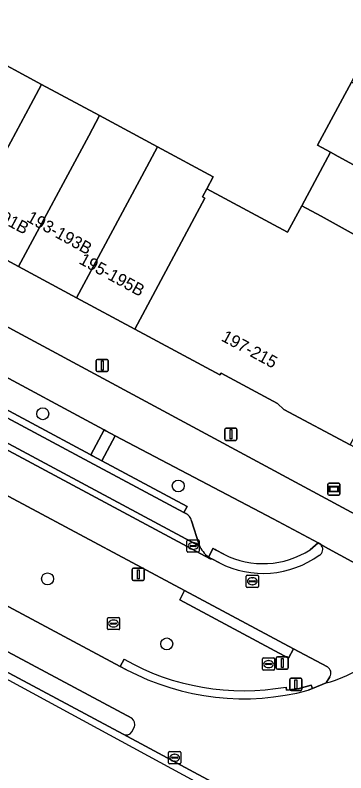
# Model space of a CAD drawing. Extents: x 159489 to 160304, y 383825 to 384531.
# Drawn here: x 159768.9 to 159796, y 383997.9 to 384059.9 of the extents above; entities that cross this region are included whole.
import ezdxf

# ---------------------------------------------------------------- set-up
doc = ezdxf.new("R2010")
doc.units = 0
for name, color, linetype in [('IMGEO_Berm_groen', 7, 'Continuous'), ('IMGEO_Berm_open', 7, 'Continuous'), ('IMGEO_Boom', 7, 'Continuous'), ('IMGEO_Erf', 7, 'Continuous'), ('IMGEO_Fietspad_gesloten', 7, 'Continuous'), ('IMGEO_Groenvoorziening', 7, 'Continuous'), ('IMGEO_Haag', 7, 'Continuous'), ('IMGEO_Informatiebord', 7, 'Continuous'), ('IMGEO_Kolk', 7, 'Continuous'), ('IMGEO_Lichtmast', 7, 'Continuous'), ('IMGEO_OVBaan_gesloten', 7, 'Continuous'), ('IMGEO_Pand', 7, 'Continuous'), ('IMGEO_Pand_nummerreeks', 7, 'Continuous'), ('IMGEO_Parkeervlak_open', 7, 'Continuous'), ('IMGEO_Rijbaan_lokaal_gesloten', 7, 'Continuous'), ('IMGEO_Rijbaan_lokaal_open', 7, 'Continuous'), ('IMGEO_Rioolput', 7, 'Continuous'), ('IMGEO_Verkeersbordpaal', 7, 'Continuous'), ('IMGEO_Voetpad_open', 7, 'Continuous')]:
    doc.layers.add(name, color=color, linetype=linetype)

msp = doc.modelspace()

# ---------------------------------------------------------------- linework, layer by layer
at = {"layer": 'IMGEO_Berm_groen'}
for points in [[(159694.802, 384052.841), (159693.976, 384051.25), (159777.482, 384006.579), (159777.79, 384007.155)], [(159794.454, 384006.529), (159791.668, 384008.018), (159791.261, 384007.258), (159782.348, 384012.022), (159782.754, 384012.782), (159722.71, 384044.871)], [(159777.06, 384025.441), (159775.963, 384023.407), (159782.969, 384019.664), (159782.699, 384019.159), (159782.841, 384019.083)], [(159793.026, 384016.123), (159793.68, 384016.677), (159789.993, 384018.658), (159777.06, 384025.441)], [(159783.314, 384018.492), (159783.95, 384016.527)], [(159784.719, 384015.525), (159785.101, 384016.235), (159785.176, 384016.179), (159785.254, 384016.128), (159785.335, 384016.083), (159785.966, 384015.746)], [(159791.06, 384004.885), (159791.106, 384004.627), (159792.127, 384004.778), (159793.112, 384005.034), (159793.224, 384004.76), (159794.349, 384005.218), (159794.65, 384005.731)]]:
    msp.add_lwpolyline(points, dxfattribs=at)
msp.add_lwpolyline([(159766.543, 384031.098), (159765.444, 384029.028), (159775.012, 384023.915), (159775.067, 384023.886), (159776.158, 384025.928), (159776.103, 384025.957)], close=True, dxfattribs=at)
for centre, radius, start, end in [((159782.548, 384018.364), 0.777, 9.50484, 67.83841), ((159785.919, 384017.242), 2.095, 199.95624, 235.05372), ((159789.168, 384022.07), 7.089, 243.14438, 302.96893), ((159787.583, 384024.482), 19.903, 240.52457, 280.06102), ((159794.145, 384006.03), 0.587, 329.35936, 58.23961), ((159791.413, 384010.841), 16.842, 277.89643, 321.28629)]:
    msp.add_arc(centre, radius, start, end, dxfattribs=at)
at = {"layer": 'IMGEO_Berm_open'}
for points in [[(159785.966, 384015.746), (159785.335, 384016.083), (159785.254, 384016.128), (159785.176, 384016.179), (159785.101, 384016.235), (159784.719, 384015.525)], [(159793.974, 384016.452), (159793.901, 384016.538), (159793.788, 384016.619), (159793.765, 384016.631), (159793.68, 384016.677), (159793.026, 384016.123)], [(159784.967, 384015.376), (159785.598, 384015.039)], [(159777.79, 384007.155), (159777.482, 384006.579), (159777.995, 384006.304)], [(159792.881, 384004.62), (159793.224, 384004.76), (159793.112, 384005.034), (159792.127, 384004.778), (159791.106, 384004.627), (159791.06, 384004.885)]]:
    msp.add_lwpolyline(points, dxfattribs=at)
msp.add_lwpolyline([(159782.754, 384012.782), (159782.348, 384012.022), (159791.261, 384007.258), (159791.668, 384008.018)], close=True, dxfattribs=at)
for centre, radius, start, end in [((159793.533, 384016.149), 0.535, 298.21231, 34.51677), ((159789.169, 384022.064), 7.881, 243.05287, 305.85797), ((159789.168, 384022.07), 7.089, 243.14438, 302.96893), ((159785.839, 384017.108), 1.939, 234.72478, 243.27978), ((159787.583, 384024.482), 19.903, 240.52457, 280.06102), ((159787.586, 384024.445), 20.52, 242.13668, 284.95487)]:
    msp.add_arc(centre, radius, start, end, dxfattribs=at)
at = {"layer": 'IMGEO_Boom'}
for centre in [(159771.136, 384027.249), (159782.231, 384021.336), (159771.522, 384013.734), (159781.289, 384008.412)]:
    msp.add_circle(centre, 0.489, dxfattribs=at)
at = {"layer": 'IMGEO_Erf'}
msp.add_lwpolyline([(159766.267, 384056.759), (159771.029, 384054.198), (159775.785, 384051.64), (159780.536, 384049.085), (159785.098, 384046.631), (159784.572, 384045.652), (159791.189, 384042.093), (159792.356, 384044.263), (159794.711, 384048.642), (159793.646, 384049.235), (159796.419, 384054.39), (159798.849, 384058.909), (159801.215, 384063.308)], dxfattribs=at)
at = {"layer": 'IMGEO_Fietspad_gesloten'}
for points in [[(159731.166, 384054.292), (159729.77, 384050.977), (159731.079, 384050.354), (159731.013, 384050.208), (159744.588, 384042.906), (159745.526, 384042.402), (159755.319, 384037.135), (159756.08, 384036.725), (159765.597, 384031.607), (159765.779, 384031.509), (159766.543, 384031.098), (159776.103, 384025.957), (159776.158, 384025.928), (159776.288, 384025.857), (159777.06, 384025.441), (159789.993, 384018.658), (159793.68, 384016.677), (159793.765, 384016.631), (159793.788, 384016.619), (159793.901, 384016.538), (159794.526, 384016.198), (159800.871, 384012.75), (159801.63, 384012.412), (159802.497, 384011.87)], [(159802.594, 384011.19), (159802.971, 384011.597), (159804.049, 384012.761), (159805.225, 384014.454), (159801.988, 384016.22), (159797.098, 384018.803), (159731.166, 384054.292)]]:
    msp.add_lwpolyline(points, dxfattribs=at)
at = {"layer": 'IMGEO_Groenvoorziening'}
for points in [[(159778.419, 384002.326), (159655.116, 384068.233), (159654.047, 384068.903), (159653.178, 384069.297)], [(159695.057, 384045.182), (159777.713, 384001.02)], [(159778.427, 384001.208), (159778.632, 384001.6)]]:
    msp.add_lwpolyline(points, dxfattribs=at)
for centre, radius, start, end in [((159778.095, 384001.837), 0.587, 336.23603, 56.46612), ((159777.966, 384001.507), 0.549, 242.50607, 326.99685)]:
    msp.add_arc(centre, radius, start, end, dxfattribs=at)
at = {"layer": 'IMGEO_Haag'}
for points in [[(159778.419, 384002.326), (159655.116, 384068.233), (159654.047, 384068.903), (159653.178, 384069.297)], [(159695.057, 384045.182), (159777.713, 384001.02)], [(159778.427, 384001.208), (159778.632, 384001.6)]]:
    msp.add_lwpolyline(points, dxfattribs=at)
for centre, radius, start, end in [((159778.095, 384001.837), 0.587, 336.23603, 56.46612), ((159777.966, 384001.507), 0.549, 242.50607, 326.99685)]:
    msp.add_arc(centre, radius, start, end, dxfattribs=at)
at = {"layer": 'IMGEO_Informatiebord'}
for p, q in [((159794.485, 384020.677), (159794.485, 384021.477)), ((159794.485, 384021.477), (159794.485, 384020.677)), ((159794.585, 384021.577), (159795.375, 384021.577)), ((159795.375, 384021.577), (159794.585, 384021.577)), ((159795.475, 384021.477), (159795.475, 384020.677)), ((159795.475, 384020.677), (159795.475, 384021.477)), ((159795.375, 384020.577), (159794.585, 384020.577)), ((159794.585, 384020.577), (159795.375, 384020.577))]:
    msp.add_line(p, q, dxfattribs=at)
for points in [[(159794.586, 384021.309), (159795.374, 384021.309), (159795.374, 384020.845), (159794.586, 384020.845), (159794.586, 384021.309)], [(159794.651, 384021.244), (159794.651, 384020.91), (159795.309, 384020.91), (159795.309, 384021.244), (159794.651, 384021.244)]]:
    msp.add_lwpolyline(points, dxfattribs=at)
for centre, start, end in [((159794.585, 384021.477), 90, 180), ((159794.585, 384021.477), 90, 180), ((159795.375, 384021.477), 0, 90), ((159795.375, 384021.477), 360, 90), ((159794.585, 384020.677), 180, 270), ((159794.585, 384020.677), 180, 270), ((159795.375, 384020.677), 270, 0), ((159795.375, 384020.677), 270, 0)]:
    msp.add_arc(centre, 0.1, start, end, dxfattribs=at)
at = {"layer": 'IMGEO_Kolk'}
for p, q in [((159782.946, 384015.998), (159782.946, 384016.85)), ((159783.021, 384016.924), (159783.873, 384016.924)), ((159783.947, 384016.85), (159783.947, 384015.998)), ((159783.205, 384016.418), (159783.205, 384016.43)), ((159783.643, 384016.381), (159783.245, 384016.381)), ((159783.248, 384016.467), (159783.646, 384016.467)), ((159783.434, 384016.704), (159783.459, 384016.704)), ((159783.689, 384016.43), (159783.689, 384016.418)), ((159783.873, 384015.924), (159783.021, 384015.924)), ((159783.457, 384016.144), (159783.432, 384016.144)), ((159787.801, 384013.114), (159787.801, 384013.966)), ((159787.876, 384014.04), (159788.728, 384014.04)), ((159788.289, 384013.82), (159788.314, 384013.82)), ((159788.802, 384013.966), (159788.802, 384013.114)), ((159788.06, 384013.534), (159788.06, 384013.546)), ((159788.498, 384013.497), (159788.1, 384013.497)), ((159788.103, 384013.583), (159788.501, 384013.583)), ((159788.312, 384013.26), (159788.287, 384013.26)), ((159788.544, 384013.546), (159788.544, 384013.534)), ((159788.728, 384013.04), (159787.876, 384013.04)), ((159776.426, 384009.654), (159776.426, 384010.506)), ((159776.501, 384010.58), (159777.353, 384010.58)), ((159776.685, 384010.074), (159776.685, 384010.086)), ((159777.123, 384010.037), (159776.725, 384010.037)), ((159776.728, 384010.123), (159777.126, 384010.123)), ((159776.914, 384010.36), (159776.939, 384010.36)), ((159777.169, 384010.086), (159777.169, 384010.074)), ((159777.427, 384010.506), (159777.427, 384009.654)), ((159777.353, 384009.58), (159776.501, 384009.58)), ((159776.937, 384009.8), (159776.912, 384009.8)), ((159789.124, 384006.338), (159789.124, 384007.19)), ((159789.199, 384007.264), (159790.051, 384007.264)), ((159789.612, 384007.044), (159789.637, 384007.044)), ((159790.125, 384007.19), (159790.125, 384006.338)), ((159789.383, 384006.758), (159789.383, 384006.77)), ((159789.821, 384006.721), (159789.423, 384006.721)), ((159789.426, 384006.807), (159789.824, 384006.807)), ((159789.635, 384006.484), (159789.61, 384006.484)), ((159789.867, 384006.77), (159789.867, 384006.758)), ((159790.051, 384006.264), (159789.199, 384006.264))]:
    msp.add_line(p, q, dxfattribs=at)
for points in [[(159782.946, 384015.998), (159782.946, 384016.85)], [(159783.021, 384016.924), (159783.873, 384016.924)], [(159783.947, 384016.85), (159783.947, 384015.998)], [(159783.873, 384015.924), (159783.021, 384015.924)], [(159787.801, 384013.114), (159787.801, 384013.966)], [(159787.876, 384014.04), (159788.728, 384014.04)], [(159788.802, 384013.966), (159788.802, 384013.114)], [(159788.728, 384013.04), (159787.876, 384013.04)], [(159776.426, 384009.654), (159776.426, 384010.506)], [(159776.501, 384010.58), (159777.353, 384010.58)], [(159777.427, 384010.506), (159777.427, 384009.654)], [(159777.353, 384009.58), (159776.501, 384009.58)], [(159789.124, 384006.338), (159789.124, 384007.19)], [(159789.199, 384007.264), (159790.051, 384007.264)], [(159790.125, 384007.19), (159790.125, 384006.338)], [(159790.051, 384006.264), (159789.199, 384006.264)]]:
    msp.add_lwpolyline(points, dxfattribs=at)
for centre, radius, start, end in [((159783.023, 384016.848), 0.0765, 91.55205, 178.44795), ((159783.023, 384016.848), 0.0765, 91.55205, 178.44795), ((159783.871, 384016.848), 0.0765, 1.55205, 88.44795), ((159783.871, 384016.848), 0.0765, 1.55205, 88.44795), ((159783.245, 384016.427), 0.0403, 85.87752, 175.75265), ((159783.242, 384016.417), 0.0366, 178.93798, 274.71019), ((159783.646, 384016.424), 0.043, 264.86636, 352.45326), ((159783.65, 384016.429), 0.0386, 1.73085, 96.63898), ((159783.023, 384016), 0.0765, 181.55205, 268.44795), ((159783.023, 384016), 0.0765, 181.55205, 268.44795), ((159783.871, 384016), 0.0765, 271.55205, 358.44795), ((159783.871, 384016), 0.0765, 271.55205, 358.44795), ((159787.878, 384013.964), 0.0765, 91.55205, 178.44795), ((159787.878, 384013.964), 0.0765, 91.55205, 178.44795), ((159788.726, 384013.964), 0.0765, 1.55205, 88.44795), ((159788.726, 384013.964), 0.0765, 1.55205, 88.44795), ((159788.1, 384013.543), 0.0403, 85.87752, 175.75265), ((159788.097, 384013.533), 0.0366, 178.93798, 274.71019), ((159788.501, 384013.54), 0.043, 264.86636, 352.45326), ((159788.505, 384013.545), 0.0386, 1.73085, 96.63898), ((159787.878, 384013.116), 0.0765, 181.55205, 268.44795), ((159787.878, 384013.116), 0.0765, 181.55205, 268.44795), ((159788.726, 384013.116), 0.0765, 271.55205, 358.44795), ((159788.726, 384013.116), 0.0765, 271.55205, 358.44795), ((159776.503, 384010.504), 0.0765, 91.55205, 178.44795), ((159776.503, 384010.504), 0.0765, 91.55205, 178.44795), ((159776.725, 384010.083), 0.0403, 85.87752, 175.75265), ((159776.722, 384010.073), 0.0366, 178.93798, 274.71019), ((159777.126, 384010.08), 0.043, 264.86636, 352.45326), ((159777.13, 384010.085), 0.0386, 1.73085, 96.63898), ((159777.351, 384010.504), 0.0765, 1.55205, 88.44795), ((159777.351, 384010.504), 0.0765, 1.55205, 88.44795), ((159776.503, 384009.656), 0.0765, 181.55205, 268.44795), ((159776.503, 384009.656), 0.0765, 181.55205, 268.44795), ((159777.351, 384009.656), 0.0765, 271.55205, 358.44795), ((159777.351, 384009.656), 0.0765, 271.55205, 358.44795), ((159789.201, 384007.188), 0.0765, 91.55205, 178.44795), ((159789.201, 384007.188), 0.0765, 91.55205, 178.44795), ((159790.049, 384007.188), 0.0765, 1.55205, 88.44795), ((159790.049, 384007.188), 0.0765, 1.55205, 88.44795), ((159789.201, 384006.34), 0.0765, 181.55205, 268.44795), ((159789.201, 384006.34), 0.0765, 181.55205, 268.44795), ((159789.423, 384006.767), 0.0403, 85.87752, 175.75265), ((159789.42, 384006.757), 0.0366, 178.93798, 274.71019), ((159789.824, 384006.764), 0.043, 264.86636, 352.45326), ((159789.828, 384006.769), 0.0386, 1.73085, 96.63898), ((159790.049, 384006.34), 0.0765, 271.55205, 358.44795), ((159790.049, 384006.34), 0.0765, 271.55205, 358.44795)]:
    msp.add_arc(centre, radius, start, end, dxfattribs=at)
for centre, major_axis, ratio, start_param, end_param in [((159783.433, 384016.424), (-0.387, 0.002), 0.722429, 4.712389, 7.853982), ((159783.458, 384016.424), (-0.39, 0.002), 0.717154, 1.570796, 4.712389), ((159788.288, 384013.54), (-0.387, 0.002), 0.722429, 4.712389, 7.853982), ((159788.313, 384013.54), (-0.39, 0.002), 0.717154, 1.570796, 4.712389), ((159776.913, 384010.08), (-0.387, 0.002), 0.722429, 4.712389, 7.853982), ((159776.938, 384010.08), (-0.39, 0.002), 0.717154, 1.570796, 4.712389), ((159789.611, 384006.764), (-0.387, 0.002), 0.722429, 4.712389, 7.853982), ((159789.636, 384006.764), (-0.39, 0.002), 0.717154, 1.570796, 4.712389)]:
    msp.add_ellipse(centre, major_axis=major_axis, ratio=ratio, start_param=start_param, end_param=end_param, dxfattribs=at)
at = {"layer": 'IMGEO_Lichtmast'}
for p, q in [((159775.511, 384030.791), (159775.511, 384031.591)), ((159775.511, 384031.591), (159775.511, 384030.791)), ((159775.611, 384031.691), (159776.401, 384031.691)), ((159776.401, 384031.691), (159775.611, 384031.691)), ((159776.501, 384031.591), (159776.501, 384030.791)), ((159776.501, 384030.791), (159776.501, 384031.591)), ((159776.401, 384030.691), (159775.611, 384030.691)), ((159775.611, 384030.691), (159776.401, 384030.691)), ((159786.049, 384025.171), (159786.049, 384025.971)), ((159786.049, 384025.971), (159786.049, 384025.171)), ((159786.149, 384026.071), (159786.939, 384026.071)), ((159786.939, 384026.071), (159786.149, 384026.071)), ((159787.039, 384025.971), (159787.039, 384025.171)), ((159787.039, 384025.171), (159787.039, 384025.971)), ((159786.939, 384025.071), (159786.149, 384025.071)), ((159786.149, 384025.071), (159786.939, 384025.071)), ((159778.46, 384013.71), (159778.46, 384014.51)), ((159778.46, 384014.51), (159778.46, 384013.71)), ((159778.56, 384014.61), (159779.35, 384014.61)), ((159779.35, 384014.61), (159778.56, 384014.61)), ((159779.45, 384014.51), (159779.45, 384013.71)), ((159779.45, 384013.71), (159779.45, 384014.51)), ((159779.35, 384013.61), (159778.56, 384013.61)), ((159778.56, 384013.61), (159779.35, 384013.61)), ((159791.369, 384004.705), (159791.369, 384005.505)), ((159791.369, 384005.505), (159791.369, 384004.705)), ((159791.469, 384005.605), (159792.259, 384005.605)), ((159792.259, 384005.605), (159791.469, 384005.605)), ((159792.359, 384005.505), (159792.359, 384004.705)), ((159792.359, 384004.705), (159792.359, 384005.505)), ((159792.259, 384004.605), (159791.469, 384004.605)), ((159791.469, 384004.605), (159792.259, 384004.605))]:
    msp.add_line(p, q, dxfattribs=at)
for points in [[(159775.931, 384031.566), (159776.081, 384031.566), (159776.081, 384030.816), (159775.931, 384030.816), (159775.931, 384031.566)], [(159786.469, 384025.946), (159786.619, 384025.946), (159786.619, 384025.196), (159786.469, 384025.196), (159786.469, 384025.946)], [(159778.88, 384014.485), (159779.03, 384014.485), (159779.03, 384013.735), (159778.88, 384013.735), (159778.88, 384014.485)], [(159791.789, 384005.48), (159791.939, 384005.48), (159791.939, 384004.73), (159791.789, 384004.73), (159791.789, 384005.48)]]:
    msp.add_lwpolyline(points, dxfattribs=at)
for centre, start, end in [((159775.611, 384031.591), 90, 180), ((159775.611, 384031.591), 90, 180), ((159776.401, 384031.591), 0, 90), ((159776.401, 384031.591), 360, 90), ((159775.611, 384030.791), 180, 270), ((159775.611, 384030.791), 180, 270), ((159776.401, 384030.791), 270, 0), ((159776.401, 384030.791), 270, 0), ((159786.149, 384025.971), 90, 180), ((159786.149, 384025.971), 90, 180), ((159786.939, 384025.971), 0, 90), ((159786.939, 384025.971), 360, 90), ((159786.149, 384025.171), 180, 270), ((159786.149, 384025.171), 180, 270), ((159786.939, 384025.171), 270, 0), ((159786.939, 384025.171), 270, 0), ((159778.56, 384014.51), 90, 180), ((159778.56, 384014.51), 90, 180), ((159779.35, 384014.51), 0, 90), ((159779.35, 384014.51), 360, 90), ((159778.56, 384013.71), 180, 270), ((159778.56, 384013.71), 180, 270), ((159779.35, 384013.71), 270, 0), ((159779.35, 384013.71), 270, 0), ((159791.469, 384005.505), 90, 180), ((159791.469, 384005.505), 90, 180), ((159792.259, 384005.505), 0, 90), ((159792.259, 384005.505), 360, 90), ((159791.469, 384004.705), 180, 270), ((159791.469, 384004.705), 180, 270), ((159792.259, 384004.705), 270, 0), ((159792.259, 384004.705), 270, 0)]:
    msp.add_arc(centre, 0.1, start, end, dxfattribs=at)
at = {"layer": 'IMGEO_OVBaan_gesloten'}
for points in [[(159777.995, 384006.304), (159777.482, 384006.579), (159693.976, 384051.25), (159656.977, 384071.043), (159654.816, 384072.267)], [(159653.178, 384069.297), (159654.047, 384068.903), (159655.116, 384068.233), (159778.419, 384002.326)], [(159794.349, 384005.218), (159793.224, 384004.76), (159792.881, 384004.62)], [(159778.632, 384001.6), (159778.427, 384001.208)], [(159777.713, 384001.02), (159792.589, 383993.049)]]:
    msp.add_lwpolyline(points, dxfattribs=at)
for centre, radius, start, end in [((159791.43, 384015.836), 11.012, 285.37083, 315.37068), ((159787.586, 384024.445), 20.52, 242.13668, 284.95487), ((159778.095, 384001.837), 0.587, 336.23603, 56.46612), ((159777.966, 384001.507), 0.549, 242.50607, 326.99685), ((159791.413, 384010.841), 16.842, 277.89643, 321.28629)]:
    msp.add_arc(centre, radius, start, end, dxfattribs=at)
at = {"layer": 'IMGEO_Pand'}
for points in [[(159770.147, 384052.559), (159771.029, 384054.198), (159766.267, 384056.759), (159765.389, 384055.118), (159759.654, 384044.398), (159764.388, 384041.852)], [(159774.902, 384050.001), (159775.785, 384051.64), (159771.029, 384054.198), (159770.147, 384052.559), (159764.388, 384041.852), (159769.137, 384039.299)], [(159808.594, 384047.531), (159798.091, 384053.448), (159796.419, 384054.39), (159793.646, 384049.235), (159794.711, 384048.642), (159795.323, 384048.301), (159796.285, 384047.766), (159804.812, 384043.02), (159805.871, 384042.465)], [(159779.655, 384047.445), (159780.536, 384049.085), (159775.785, 384051.64), (159774.902, 384050.001), (159769.137, 384039.299), (159773.904, 384036.736)], [(159784.42, 384044.886), (159784.211, 384044.994), (159784.572, 384045.652), (159785.098, 384046.631), (159780.536, 384049.085), (159779.655, 384047.445), (159773.904, 384036.736), (159778.666, 384034.176)], [(159796.285, 384047.766), (159795.323, 384048.301), (159794.711, 384048.642), (159792.356, 384044.263), (159793.941, 384043.41), (159802.47, 384038.666), (159804.812, 384043.02)], [(159778.666, 384034.176), (159785.645, 384030.424), (159785.732, 384030.559), (159790.367, 384028.077), (159790.874, 384027.608), (159796.313, 384024.693), (159797.928, 384027.689), (159803.527, 384038.097), (159802.47, 384038.666), (159793.941, 384043.41), (159792.356, 384044.263), (159791.189, 384042.093), (159784.572, 384045.652), (159784.211, 384044.994), (159784.42, 384044.886)]]:
    msp.add_lwpolyline(points, close=True, dxfattribs=at)
at = {"layer": 'IMGEO_Parkeervlak_open'}
for points in [[(159735.114, 384044.297), (159732.479, 384043.633), (159733.023, 384043.708), (159783.959, 384016.413), (159783.95, 384016.527), (159783.314, 384018.492)], [(159782.841, 384019.083), (159782.699, 384019.159), (159775.691, 384022.903), (159774.939, 384023.305), (159765.175, 384028.522), (159764.408, 384028.932), (159754.714, 384034.111)]]:
    msp.add_lwpolyline(points, dxfattribs=at)
msp.add_arc((159782.548, 384018.364), 0.777, 9.50484, 67.83841, dxfattribs=at)
at = {"layer": 'IMGEO_Rijbaan_lokaal_gesloten'}
for points in [[(159695.057, 384045.182), (159805.451, 383985.323), (159805.834, 383985.948), (159792.589, 383993.049), (159777.713, 384001.02), (159695.057, 384045.182)], [(159722.71, 384044.871), (159782.754, 384012.782), (159791.668, 384008.018), (159794.454, 384006.529)], [(159785.598, 384015.039), (159784.967, 384015.376), (159784.85, 384015.386), (159732.397, 384043.459), (159732.479, 384043.633), (159731.607, 384043.881)], [(159800.665, 384012.823), (159800.768, 384012.787), (159800.871, 384012.75), (159794.526, 384016.198), (159793.901, 384016.538), (159793.974, 384016.452)], [(159794.65, 384005.731), (159794.349, 384005.218)]]:
    msp.add_lwpolyline(points, dxfattribs=at)
for centre, radius, start, end in [((159793.533, 384016.149), 0.535, 298.21231, 34.51677), ((159789.169, 384022.064), 7.881, 243.05287, 305.85797), ((159791.43, 384015.836), 11.012, 285.37083, 315.37068), ((159794.145, 384006.03), 0.587, 329.35936, 58.23961)]:
    msp.add_arc(centre, radius, start, end, dxfattribs=at)
at = {"layer": 'IMGEO_Rijbaan_lokaal_open'}
for points in [[(159733.023, 384043.708), (159732.479, 384043.633), (159732.397, 384043.459), (159784.85, 384015.386), (159784.967, 384015.376)], [(159783.95, 384016.527), (159783.959, 384016.413), (159733.023, 384043.708)]]:
    msp.add_lwpolyline(points, dxfattribs=at)
for centre, radius, start, end in [((159785.919, 384017.242), 2.095, 199.95624, 235.05372), ((159785.839, 384017.108), 1.939, 234.72478, 243.27978)]:
    msp.add_arc(centre, radius, start, end, dxfattribs=at)
at = {"layer": 'IMGEO_Rioolput'}
for p, q in [((159781.433, 383998.674), (159781.433, 383999.526)), ((159781.508, 383999.6), (159782.36, 383999.6)), ((159782.434, 383999.526), (159782.434, 383998.674)), ((159781.692, 383999.094), (159781.692, 383999.106)), ((159782.13, 383999.057), (159781.732, 383999.057)), ((159781.735, 383999.143), (159782.133, 383999.143)), ((159781.921, 383999.38), (159781.946, 383999.38)), ((159782.176, 383999.106), (159782.176, 383999.094)), ((159782.36, 383998.6), (159781.508, 383998.6)), ((159781.944, 383998.82), (159781.919, 383998.82))]:
    msp.add_line(p, q, dxfattribs=at)
for points in [[(159781.433, 383998.674), (159781.433, 383999.526)], [(159781.508, 383999.6), (159782.36, 383999.6)], [(159782.434, 383999.526), (159782.434, 383998.674)], [(159782.36, 383998.6), (159781.508, 383998.6)]]:
    msp.add_lwpolyline(points, dxfattribs=at)
for centre, radius, start, end in [((159781.51, 383999.524), 0.0765, 91.55205, 178.44795), ((159781.51, 383999.524), 0.0765, 91.55205, 178.44795), ((159782.358, 383999.524), 0.0765, 1.55205, 88.44795), ((159782.358, 383999.524), 0.0765, 1.55205, 88.44795), ((159781.732, 383999.103), 0.0403, 85.87752, 175.75265), ((159781.729, 383999.093), 0.0366, 178.93798, 274.71019), ((159782.133, 383999.1), 0.043, 264.86636, 352.45326), ((159782.137, 383999.105), 0.0386, 1.73085, 96.63898), ((159781.51, 383998.676), 0.0765, 181.55205, 268.44795), ((159781.51, 383998.676), 0.0765, 181.55205, 268.44795), ((159782.358, 383998.676), 0.0765, 271.55205, 358.44795), ((159782.358, 383998.676), 0.0765, 271.55205, 358.44795)]:
    msp.add_arc(centre, radius, start, end, dxfattribs=at)
for centre, major_axis, ratio, start_param, end_param in [((159781.92, 383999.1), (-0.387, 0.002), 0.722429, 4.712389, 7.853982), ((159781.945, 383999.1), (-0.39, 0.002), 0.717154, 1.570796, 4.712389)]:
    msp.add_ellipse(centre, major_axis=major_axis, ratio=ratio, start_param=start_param, end_param=end_param, dxfattribs=at)
at = {"layer": 'IMGEO_Verkeersbordpaal'}
for p, q in [((159790.256, 384006.458), (159790.256, 384007.258)), ((159790.256, 384007.258), (159790.256, 384006.458)), ((159790.356, 384007.358), (159791.146, 384007.358)), ((159791.146, 384007.358), (159790.356, 384007.358)), ((159791.246, 384007.258), (159791.246, 384006.458)), ((159791.246, 384006.458), (159791.246, 384007.258)), ((159791.146, 384006.358), (159790.356, 384006.358)), ((159790.356, 384006.358), (159791.146, 384006.358))]:
    msp.add_line(p, q, dxfattribs=at)
msp.add_lwpolyline([(159790.676, 384007.233), (159790.826, 384007.233), (159790.826, 384006.483), (159790.676, 384006.483), (159790.676, 384007.233)], dxfattribs=at)
for centre, start, end in [((159790.356, 384007.258), 90, 180), ((159790.356, 384007.258), 90, 180), ((159791.146, 384007.258), 0, 90), ((159791.146, 384007.258), 360, 90), ((159790.356, 384006.458), 180, 270), ((159790.356, 384006.458), 180, 270), ((159791.146, 384006.458), 270, 0), ((159791.146, 384006.458), 270, 0)]:
    msp.add_arc(centre, 0.1, start, end, dxfattribs=at)
at = {"layer": 'IMGEO_Voetpad_open'}
for points in [[(159748.885, 384052.879), (159745.177, 384054.872), (159744.059, 384052.782), (159744, 384052.814), (159737.293, 384056.412), (159733.379, 384058.49), (159731.166, 384054.292), (159797.098, 384018.803), (159799.393, 384023.037), (159796.313, 384024.693), (159790.874, 384027.608), (159790.367, 384028.077), (159785.732, 384030.559), (159785.645, 384030.424), (159778.666, 384034.176), (159773.904, 384036.736), (159769.137, 384039.299), (159764.388, 384041.852), (159759.654, 384044.398), (159754.877, 384046.966), (159747.838, 384050.751), (159747.763, 384050.791)], [(159777.06, 384025.441), (159776.288, 384025.857), (159776.158, 384025.928), (159775.067, 384023.886), (159775.207, 384023.811), (159775.963, 384023.407)]]:
    msp.add_lwpolyline(points, close=True, dxfattribs=at)
msp.add_lwpolyline([(159735.862, 384044.184), (159743.356, 384040.18), (159744.117, 384039.773), (159753.949, 384034.52), (159754.714, 384034.111), (159764.408, 384028.932), (159765.175, 384028.522), (159774.939, 384023.305), (159775.691, 384022.903), (159782.699, 384019.159), (159782.969, 384019.664), (159775.963, 384023.407), (159775.207, 384023.811), (159775.067, 384023.886), (159775.012, 384023.915), (159765.444, 384029.028), (159764.677, 384029.438), (159764.491, 384029.537), (159754.979, 384034.619)], dxfattribs=at)

# ---------------------------------------------------------------- texts
at = {"layer": 'IMGEO_Pand_nummerreeks'}
for s, rotation, p in [('191-191B', 331.78183, (159764.533, 384044.627)), ('193-193B', 331.08855, (159769.73, 384043.027)), ('195-195B', 331.42659, (159774.026, 384039.574)), ('197-215', 331.60705, (159785.68, 384033.261))]:
    msp.add_text(s, height=1, rotation=rotation, dxfattribs=at).set_placement(p)

doc.saveas('drawing.dxf')
